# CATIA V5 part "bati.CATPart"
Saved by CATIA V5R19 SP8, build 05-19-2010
Part number: bati
Publications: "axeFbis", "axebbis", "axeAbis", "axerainure"
Bounding box of the stored display mesh (mm): x -20 to 20, y -80 to 200, z 0 to 80
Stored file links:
  C:\Users\rcousturie\Desktop\EU_thinkMotion\iao\IAO_MMS_Groupe1\flamrini\Lamrini_projet_IAO2011\Lamrini_projet_IAO2011\projet_iao_traindatterrissage\projet_iao_traindatterrissage\bati.CATPart
  C:\Users\rcousturie\Desktop\EU_thinkMotion\iao\IAO_MMS_Groupe1\flamrini\Lamrini_projet_IAO2011\Lamrini_projet_IAO2011\projet_iao_traindatterrissage\projet_iao_traindatterrissage\squelettetrain.CATProduct
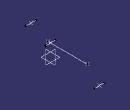
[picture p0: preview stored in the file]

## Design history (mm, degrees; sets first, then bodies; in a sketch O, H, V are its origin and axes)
Set1
  Point1 "PointF": linked copy from another document
  Point2 "Pointb": linked copy from another document
  Point3 "PointA": linked copy from another document
  Point4: linked copy from another document
  Point5: linked copy from another document
Set2 "Set géométrique.6"
  Line1 "axeFbis": type PtDir, RefPoint Point1, Direction yz-plane, Start -20, End 20
  Line2 "axebbis": type PtDir, RefPoint Point2, Direction yz-plane, Start -20, End 20
  Line3 "axeAbis": type PtDir, RefPoint Point3, Direction yz-plane, Start -20, End 20
  Line4 "axerainure": type PtPt, FirstPoint Point4, SecondPoint Point5
Body1 (main body)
